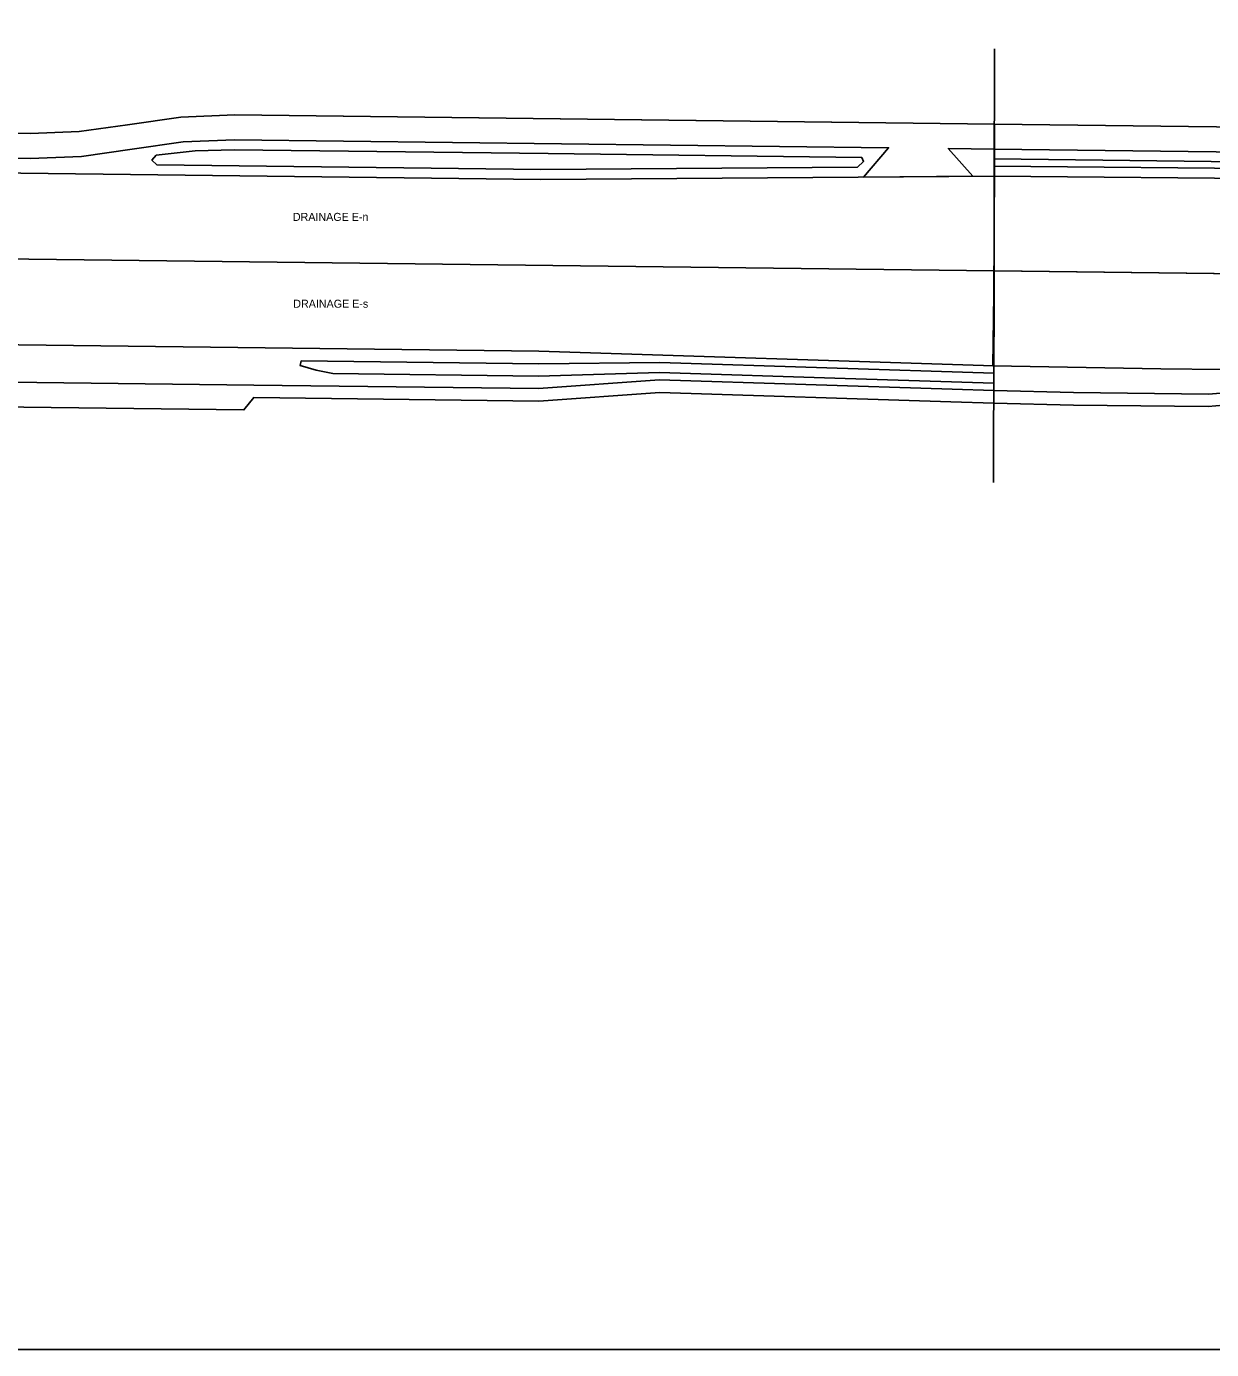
# Model space of a CAD drawing. Extents: x 2342969 to 2348591, y 2217407 to 2218312.
# Drawn here: x 2347638 to 2348114, y 2217407 to 2217938 of the extents above; entities that cross this region are included whole.
import ezdxf

# ---------------------------------------------------------------- set-up
doc = ezdxf.new("R2010")
doc.units = 0
doc.layers.add('TOPO_CURBGTR_Lip-of-Gutter', color=7, linetype='Continuous')
doc.layers.add('TOPO_SW_Edge', color=7, linetype='Continuous')

msp = doc.modelspace()

# ---------------------------------------------------------------- linework, layer by layer
at = {"layer": 'TOPO_CURBGTR_Lip-of-Gutter'}
for p, q in [((2348027.19, 2217929.39), (2348026.82, 2217755.11)), ((2348027.1, 2217885.19), (2348027.09, 2217882.33))]:
    msp.add_line(p, q, dxfattribs=at)
for points in [[(2346465.43, 2217922.67), (2346464.66, 2217859.17), (2348027, 2217840.19), (2348027.13, 2217899.19), (2347874.53, 2217901.04), (2347721.93, 2217902.9), (2347700.27, 2217902.04), (2347678.82, 2217898.96), (2347659.4, 2217896.17), (2347639.81, 2217895.39), (2347444.37, 2217897.77), (2347429.75, 2217899.02), (2347415.47, 2217902.41), (2347399.75, 2217906.13), (2347383.67, 2217907.51), (2347312.05, 2217908.38), (2347240.42, 2217909.25), (2347040.49, 2217915.68)], [(2346465.13, 2217897.67), (2347040.08, 2217890.68), (2347240.02, 2217884.25), (2347844.98, 2217876.9), (2348027.08, 2217878.33), (2348027, 2217840.19), (2346464.66, 2217859.17)], [(2348027.13, 2217899.19), (2348361.5, 2217895.13), (2348404.43, 2217890.17), (2348415.32, 2217900.78), (2348425.98, 2217900.55), (2348446.16, 2217882.55), (2348445.89, 2217835.1), (2348027, 2217840.19)], [(2348027.13, 2217899.19), (2348027.11, 2217889.19), (2348361.38, 2217885.13), (2348372.08, 2217884.36), (2348395.07, 2217881.32), (2348404.43, 2217890.17), (2348361.5, 2217895.13)], [(2347690.64, 2217882.78), (2347767.83, 2217881.84), (2347844.94, 2217880.9), (2347972.2, 2217881.9), (2347974.61, 2217884.18), (2347973.87, 2217885.83), (2347847.81, 2217887.37), (2347721.76, 2217888.9), (2347706.02, 2217888.46), (2347690.37, 2217886.75), (2347688.67, 2217884.64)], [(2348027, 2217840.19), (2348027.08, 2217878.33), (2348145, 2217877.25), (2348297.61, 2217872.4), (2348341.49, 2217871.86), (2348385.37, 2217871.32), (2348446.16, 2217882.55), (2348445.89, 2217835.1)], [(2348027.1, 2217885.19), (2348027.09, 2217882.33), (2348145.05, 2217881.25), (2348297.74, 2217876.4), (2348378.77, 2217875.42), (2348380.79, 2217877.27), (2348379.06, 2217879.4), (2348371.56, 2217880.39), (2348361.33, 2217881.13), (2348190.6, 2217883.2)], [(2346464.66, 2217859.17), (2348027, 2217840.18), (2348026.89, 2217787.07), (2348009.69, 2217787.62), (2347892.7, 2217791.38), (2347844.1, 2217787.9), (2347729.58, 2217789.3), (2347725.62, 2217784.34), (2347482.3, 2217787.3), (2347238.98, 2217790.26), (2347038.94, 2217788.69), (2346728.44, 2217792.46), (2346463.89, 2217795.68)], [(2346464.66, 2217859.17), (2346464.19, 2217820.67), (2347039.15, 2217813.69), (2347239.18, 2217815.26), (2347844.14, 2217807.9), (2348026.92, 2217802.03), (2348027, 2217840.18)], [(2348027, 2217840.19), (2348026.54, 2217802.03), (2348094.07, 2217800.87), (2348144.07, 2217800.26), (2348220.41, 2217800.83), (2348296.75, 2217801.4), (2348341.02, 2217800.72), (2348383.98, 2217800.19), (2348395.21, 2217798.23), (2348445.66, 2217793.89), (2348445.89, 2217835.1)], [(2348027.38, 2217840.18), (2348445.89, 2217835.1), (2348445.66, 2217793.89), (2348395.91, 2217783.83), (2348389.1, 2217784.07), (2348378.75, 2217777.41), (2348220.09, 2217779.33), (2348207.85, 2217781.19), (2348196.59, 2217786.3), (2348186.19, 2217790.95), (2348174.9, 2217792.49), (2348146.29, 2217792.28), (2348131.09, 2217789.15), (2348122.27, 2217786.47), (2348113.1, 2217785.64), (2348058.89, 2217786.29), (2348026.89, 2217787.07), (2348027, 2217840.18)], [(2346464.01, 2217805.67), (2347038.97, 2217798.69), (2347239, 2217800.26), (2347729.64, 2217794.3), (2347843.95, 2217792.91), (2347892.61, 2217796.39), (2348010.22, 2217792.61), (2348026.9, 2217792.07), (2348026.89, 2217787.07), (2348009.69, 2217787.62), (2347892.7, 2217791.38), (2347844.1, 2217787.9), (2347729.58, 2217789.3), (2347725.62, 2217784.34), (2347238.98, 2217790.26), (2347038.94, 2217788.69), (2346463.89, 2217795.68)], [(2347748.66, 2217804.06), (2347748.25, 2217802.14), (2347754.67, 2217800.28), (2347761.36, 2217798.91), (2347844.02, 2217797.91), (2347892.64, 2217799.39), (2347967.22, 2217796.99), (2348026.9, 2217795.07), (2348026.91, 2217799.07), (2347892.69, 2217803.39), (2347844.08, 2217802.91)]]:
    msp.add_lwpolyline(points, close=True, dxfattribs=at)
for points in [[(2347444.25, 2217887.77), (2347639.69, 2217885.39), (2347660.31, 2217886.21), (2347680.75, 2217889.15), (2347701.18, 2217892.08), (2347721.81, 2217892.9), (2347984.64, 2217889.7), (2347974.5, 2217877.92), (2348018.5, 2217878.26), (2348008.64, 2217889.41), (2348027.11, 2217889.19), (2348027.13, 2217899.19), (2347721.93, 2217902.9), (2347700.27, 2217902.04), (2347678.82, 2217898.96), (2347659.4, 2217896.17), (2347639.81, 2217895.39), (2347444.37, 2217897.77)], [(2348122.27, 2217786.47), (2348113.1, 2217785.64), (2348058.89, 2217786.29), (2348026.89, 2217787.07), (2348026.9, 2217792.07), (2348058.95, 2217791.29), (2348113.16, 2217790.63), (2348121.31, 2217791.37)]]:
    msp.add_lwpolyline(points, dxfattribs=at)
at = {"layer": 'TOPO_SW_Edge'}
msp.add_lwpolyline([(2345930.36, 2218312.45), (2348590.54, 2218312.45), (2348590.54, 2217406.65), (2345930.36, 2217406.65)], close=True, dxfattribs=at)

# ---------------------------------------------------------------- texts
for s, p in [('DRAINAGE E-n', (2347745.28, 2217860.3)), ('DRAINAGE E-s', (2347745.45, 2217825.4))]:
    msp.add_text(s, height=3.216, dxfattribs=at).set_placement(p)

doc.saveas('drawing.dxf')
